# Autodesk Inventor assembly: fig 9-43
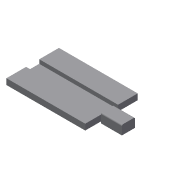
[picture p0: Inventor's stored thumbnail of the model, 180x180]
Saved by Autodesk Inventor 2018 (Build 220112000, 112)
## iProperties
Created: 2013-07
Part Number: fig 9-43
Document SubType Name: Assembly
Designer: CADCIM
Author: CADCIM
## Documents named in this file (3)
- E:\_Deepak\Inventor\Autodesk Inventor_2017_Project\Resources\Inventor_2018_Part\c09_Inv_2018\c09_inv_2018_prt\fig 9-43.iam
- E:\_Deepak\Inventor\Autodesk Inventor_2017_Project\Resources\Inventor_2018_Part\c09_Inv_2018\c09_inv_2018_prt\15.ipt
- E:\_Deepak\Inventor\Autodesk Inventor_2017_Project\Resources\Inventor_2018_Part\c09_Inv_2018\c09_inv_2018_prt\16.ipt
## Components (2 placed, 2 different names)
1. 15:1
2. 16:1
